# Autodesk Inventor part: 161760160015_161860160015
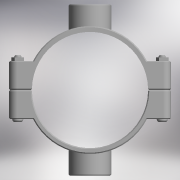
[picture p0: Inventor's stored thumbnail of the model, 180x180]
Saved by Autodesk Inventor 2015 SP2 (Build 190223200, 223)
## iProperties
Created: 2017-05
Part Number: 161760160015_161860160015
Material: Generic
Description: PLASSON DOUBLE SADDLE 160-1.1/2"
Document SubType Name: Modeling
Designer: KIM
Density: 1 g/cm^3
Appearance: Default
Author: KIM
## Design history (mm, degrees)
derived "16176.ipt"
feature "Solid1::16176.ipt"
feature "Solid2::16176.ipt"
tag "TaggingFeature1"
body "Solid1"
body "Solid2"
other parameters: "d0" = 176, "d1" = 223, "d4" = 145, "d5" = 0, "d6" = 11.15, "d7" = 223, "d8" = 0.1, "d10" = 0, "d11" = 1.6, "d20" = 1.6, "d23" = 1.6, "d36" = 15, "d37" = 12, "d38" = 88, "d39" = 0, "d40" = 3, "d41" = 5, "d42" = 0, "d44" = 3, "d45" = 0, "d46" = 1.6, "d52" = 44.845, "d53" = 25, "d54" = 0, "d57" = 0, "d58" = 172.8, "d60" = 0, "d62" = 15, "d63" = 12, "d66" = 121, "d67" = 236, "d68" = 58.2985, "d69" = 44.845, "d70" = 25, "d71" = 0, "d74" = 0, "d75" = 1.6, "G_" = 44.845, "A_" = 118, "L_" = 223, "L_1" = 145, "l_2" = 25
